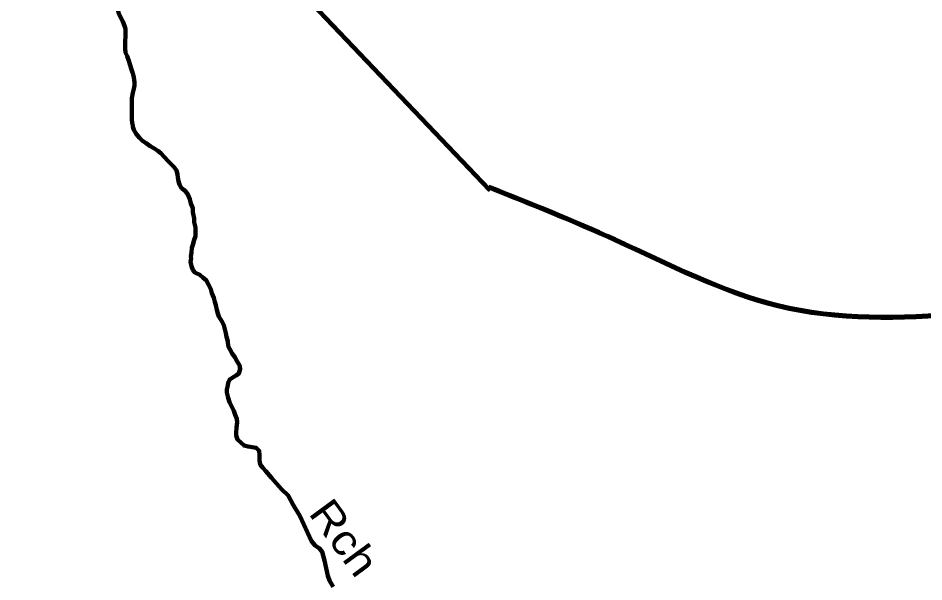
# Model space of a CAD drawing. Extents: x -1643653 to 4543381, y 1624270 to 13878484.
# Drawn here: x 660376 to 675404, y 8927410 to 8936763 of the extents above; entities that cross this region are included whole.
import ezdxf

# ---------------------------------------------------------------- set-up
doc = ezdxf.new("R2010")
doc.units = 0
doc.header["$LTSCALE"] = 200
for name, color, linetype, lineweight in [('1', 7, 'Continuous', 13), ('24', 7, 'Continuous', 25), ('26', 7, 'Continuous', 106), ('27', 7, 'Continuous', 53), ('28', 7, 'Continuous', 53), ('53', 7, 'Continuous', 106)]:
    doc.layers.add(name, color=color, linetype=linetype, lineweight=lineweight)
doc.layers.add('49', color=7, linetype='Continuous')

msp = doc.modelspace()

# ---------------------------------------------------------------- linework, layer by layer
at = {"layer": '1', "lineweight": 25}
msp.add_spline([(814781, 9009175.5), (814787.2, 9009173.4), (814796.9, 9009173.4), (814799.4, 9009172.4), (814805.1, 9009174.5), (814805.6, 9009176.5), (814811.7, 9009179.5), (814811.7, 9009179.5), (814801.5, 9009181), (814790.7, 9009181.5), (814784.1, 9009183.1), (814777.4, 9009185.1), (814778.4, 9009175.5)], degree=3, dxfattribs=at)
at = {"layer": '24'}
for points in [[(662269, 8935879), (662260.1, 8935911.3), (662230.5, 8935996.6), (662213.3, 8936054.2), (662186.1, 8936131.9), (662158.9, 8936194.6), (662154.1, 8936254.7), (662155.7, 8936587.5), (662143.4, 8936635.1), (662116.2, 8936705.3), (662081.5, 8936768.1), (662044.3, 8936850.8), (662029.6, 8936926), (662017.4, 8936983.6), (661987.8, 8937066.3), (661980.6, 8937131.4), (661965.8, 8937179), (661940.2, 8937257.2)], [(662278.1, 8934978.8), (662271.1, 8935027.9), (662261.3, 8935080.5), (662262.9, 8935433.3), (662280.9, 8935523.3), (662293.7, 8935590.8), (662306.4, 8935643.3), (662306.7, 8935698.4), (662297.1, 8935778.5), (662277.4, 8935848.7), (662269, 8935879)], [(663047.1, 8934021.1), (663034.8, 8934060.5), (663027.5, 8934120.6), (663020.3, 8934175.7), (663003, 8934235.8), (662963.2, 8934288.6), (662920.9, 8934333.8), (662866.1, 8934389.2), (662801.4, 8934459.6), (662746.6, 8934519.9), (662696.8, 8934562.7), (662626.9, 8934603.1), (662567, 8934636), (662499.7, 8934688.9), (662439.8, 8934726.7), (662390, 8934779.5), (662332.8, 8934842.4), (662298, 8934907.6), (662280.8, 8934960.3), (662278.1, 8934978.8)], [(663089.3, 8933942.6), (663052, 8934005.3), (663047.1, 8934021.1)], [(663996.4, 8929884.7), (663996.8, 8929971.2), (664009.7, 8930053.7), (664007.4, 8930113.8), (663977.7, 8930184), (663958, 8930249.2), (663913.4, 8930334.5), (663886.1, 8930392.2), (663858.9, 8930462.4), (663839.3, 8930550.1), (663839.5, 8930602.7), (663854.8, 8930667.7), (663860.1, 8930715.2), (663887.8, 8930767.6), (663945.6, 8930807.4), (663995.7, 8930834.6), (664041, 8930869.4), (664061.3, 8930941.9), (664046.6, 8931004.6), (664011.8, 8931064.8), (663969.6, 8931137.6), (663929.9, 8931197.9), (663890.2, 8931270.7), (663862.9, 8931320.8), (663855.7, 8931401), (663836.1, 8931476.2), (663821.3, 8931533.8), (663804.1, 8931601.4), (663786.9, 8931666.6), (663759.6, 8931724.3), (663734.8, 8931769.5), (663707.5, 8931812.2), (663690.2, 8931859.8), (663675.5, 8931924.9), (663658.3, 8932002.6), (663638.6, 8932057.8), (663621.3, 8932120.4), (663589.2, 8932200.7), (663572, 8932265.8), (663534.8, 8932343.6), (663497.6, 8932413.9), (663447.7, 8932454.2), (663390.4, 8932504.5), (663310.5, 8932545), (663277, 8932589.1), (663254.9, 8932645.9), (663239.1, 8932721.7), (663245.4, 8932772.2), (663244.2, 8932810.6), (663254.5, 8932873.1), (663257.3, 8932950.7), (663275.1, 8933003.2), (663298, 8933083.1), (663318.3, 8933145.6), (663321.2, 8933225.6), (663319, 8933288.2), (663299.3, 8933375.9), (663297.1, 8933436), (663277.6, 8933543.7), (663272.9, 8933611.3), (663240.7, 8933686.5), (663226, 8933756.7), (663191.4, 8933839.4), (663146.6, 8933897.2), (663089.3, 8933942.6)], [(665604.7, 8927327.2), (665543.5, 8927435.1), (665514.2, 8927508.8), (665462.2, 8927764.8), (665420, 8927905.9), (665377.5, 8927963.9), (665304.4, 8928016.2), (665243.3, 8928087.8), (665050.8, 8928503.2), (664941.5, 8928686.6), (664858.3, 8928844.6), (664746.5, 8928950.8), (664577.8, 8929135.4), (664488.9, 8929245.3), (664434.1, 8929300.7), (664391.8, 8929358.5), (664382.1, 8929428.6), (664380, 8929511.2), (664377.8, 8929583.8), (664325.5, 8929634.1), (664258, 8929647), (664193, 8929654.8), (664125.5, 8929670.2), (664070.7, 8929720.5), (664013.4, 8929773.4), (663996.1, 8929836.1), (663996.4, 8929884.7)]]:
    msp.add_lwpolyline(points, dxfattribs=at)
at = {"layer": '26'}
for points in [[(645793.1, 8949290.9), (653495.4, 8947850), (659002.1, 8941889), (662654, 8939737.7), (668185.2, 8933928.8)], [(661559, 8940382.7), (662654, 8939737.7), (668185.2, 8933928.8)]]:
    msp.add_lwpolyline(points, dxfattribs=at)
msp.add_spline([(668185.2, 8933965.5), (670277.1, 8933094.3), (672981.1, 8931999.5), (676061.1, 8931869.5), (681079.4, 8933269.5), (681670, 8933656.4)], degree=3, dxfattribs=at)
at = {"layer": '27'}
msp.add_lwpolyline([(665419.6, 8936833.2), (668185.2, 8933928.8), (668185.2, 8933965.5)], dxfattribs=at)
msp.add_spline([(668185.2, 8933965.5), (670277.1, 8933094.3), (672981.1, 8931999.5), (676061.1, 8931869.5), (681079.4, 8933269.5), (681670, 8933656.4)], degree=3, dxfattribs=at)
at = {"layer": '28'}
for points in [[(661559, 8940382.7), (662654, 8939737.7), (668185.2, 8933928.8), (668185.2, 8933965.5)], [(661559, 8940356.6), (662654, 8939711.5), (668185.2, 8933902.6), (668185.2, 8933939.4)]]:
    msp.add_lwpolyline(points, dxfattribs=at)
for points in [[(668185.2, 8933965.5), (670277.1, 8933094.3), (672981.1, 8931999.5), (676061.1, 8931869.5), (681079.4, 8933269.5), (681670, 8933656.4)], [(668185.2, 8933939.4), (670277.1, 8933068.1), (672981.1, 8931973.4), (676061.1, 8931843.3), (681079.4, 8933243.3), (681670, 8933630.2)]]:
    msp.add_spline(points, degree=3, dxfattribs=at)
at = {"layer": '53'}
for points in [[(662269, 8935879), (662260.1, 8935911.3), (662230.5, 8935996.6), (662213.3, 8936054.2), (662186.1, 8936131.9), (662158.9, 8936194.6), (662154.1, 8936254.7), (662155.7, 8936587.5), (662143.4, 8936635.1), (662116.2, 8936705.3), (662081.5, 8936768.1), (662044.3, 8936850.8), (662029.6, 8936926), (662017.4, 8936983.6), (661987.8, 8937066.3), (661980.6, 8937131.4), (661965.8, 8937179), (661940.2, 8937257.2)], [(662278.1, 8934978.8), (662271.1, 8935027.9), (662261.3, 8935080.5), (662262.9, 8935433.3), (662280.9, 8935523.3), (662293.7, 8935590.8), (662306.4, 8935643.3), (662306.7, 8935698.4), (662297.1, 8935778.5), (662277.4, 8935848.7), (662269, 8935879)], [(663047.1, 8934021.1), (663034.8, 8934060.5), (663027.5, 8934120.6), (663020.3, 8934175.7), (663003, 8934235.8), (662963.2, 8934288.6), (662920.9, 8934333.8), (662866.1, 8934389.2), (662801.4, 8934459.6), (662746.6, 8934519.9), (662696.8, 8934562.7), (662626.9, 8934603.1), (662567, 8934636), (662499.7, 8934688.9), (662439.8, 8934726.7), (662390, 8934779.5), (662332.8, 8934842.4), (662298, 8934907.6), (662280.8, 8934960.3), (662278.1, 8934978.8)], [(663089.3, 8933942.6), (663052, 8934005.3), (663047.1, 8934021.1)], [(663996.4, 8929884.7), (663996.8, 8929971.2), (664009.7, 8930053.7), (664007.4, 8930113.8), (663977.7, 8930184), (663958, 8930249.2), (663913.4, 8930334.5), (663886.1, 8930392.2), (663858.9, 8930462.4), (663839.3, 8930550.1), (663839.5, 8930602.7), (663854.8, 8930667.7), (663860.1, 8930715.2), (663887.8, 8930767.6), (663945.6, 8930807.4), (663995.7, 8930834.6), (664041, 8930869.4), (664061.3, 8930941.9), (664046.6, 8931004.6), (664011.8, 8931064.8), (663969.6, 8931137.6), (663929.9, 8931197.9), (663890.2, 8931270.7), (663862.9, 8931320.8), (663855.7, 8931401), (663836.1, 8931476.2), (663821.3, 8931533.8), (663804.1, 8931601.4), (663786.9, 8931666.6), (663759.6, 8931724.3), (663734.8, 8931769.5), (663707.5, 8931812.2), (663690.2, 8931859.8), (663675.5, 8931924.9), (663658.3, 8932002.6), (663638.6, 8932057.8), (663621.3, 8932120.4), (663589.2, 8932200.7), (663572, 8932265.8), (663534.8, 8932343.6), (663497.6, 8932413.9), (663447.7, 8932454.2), (663390.4, 8932504.5), (663310.5, 8932545), (663277, 8932589.1), (663254.9, 8932645.9), (663239.1, 8932721.7), (663245.4, 8932772.2), (663244.2, 8932810.6), (663254.5, 8932873.1), (663257.3, 8932950.7), (663275.1, 8933003.2), (663298, 8933083.1), (663318.3, 8933145.6), (663321.2, 8933225.6), (663319, 8933288.2), (663299.3, 8933375.9), (663297.1, 8933436), (663277.6, 8933543.7), (663272.9, 8933611.3), (663240.7, 8933686.5), (663226, 8933756.7), (663191.4, 8933839.4), (663146.6, 8933897.2), (663089.3, 8933942.6)], [(665604.7, 8927327.2), (665543.5, 8927435.1), (665514.2, 8927508.8), (665462.2, 8927764.8), (665420, 8927905.9), (665377.5, 8927963.9), (665304.4, 8928016.2), (665243.3, 8928087.8), (665050.8, 8928503.2), (664941.5, 8928686.6), (664858.3, 8928844.6), (664746.5, 8928950.8), (664577.8, 8929135.4), (664488.9, 8929245.3), (664434.1, 8929300.7), (664391.8, 8929358.5), (664382.1, 8929428.6), (664380, 8929511.2), (664377.8, 8929583.8), (664325.5, 8929634.1), (664258, 8929647), (664193, 8929654.8), (664125.5, 8929670.2), (664070.7, 8929720.5), (664013.4, 8929773.4), (663996.1, 8929836.1), (663996.4, 8929884.7)]]:
    msp.add_lwpolyline(points, dxfattribs=at)

# ---------------------------------------------------------------- texts
at = {"layer": '49', "width": 1.15}
msp.add_text('Rch', height=500, rotation=306.272, dxfattribs=at).set_placement((665180.9, 8928547.7))

doc.saveas('drawing.dxf')
